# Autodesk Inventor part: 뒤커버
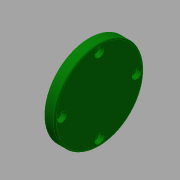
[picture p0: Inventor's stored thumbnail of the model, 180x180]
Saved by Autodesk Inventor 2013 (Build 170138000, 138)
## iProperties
Created: 2015-09
Part Number: 뒤커버
Material: 알루미늄 6061
Document SubType Name: Modeling
Designer: mduedu
Density: 2.71 g/cm^3
Mass: 54.0417 g
Surface Area: 84.9688 cm^2
Volume: 19.9416 cm^3
Author: mduedu
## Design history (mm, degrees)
sketch "스케치1"
  geometry: L1 (-15.5, 47)-(-15.5, 78); L2 (-15.5, 78)-(-22.5, 78); L3 (-22.5, 78)-(-22.5, 63); L4 (-28.5, 63)-(-28.5, 47); L5 (-79.5, 39.5)-(-79.5, 54.5) reference; L6 (48.5, 54.5)-(48.5, 39.5) reference; L7 (-79.5, 47)-(48.5, 47); L8 (-22.5, 63)-(-28.5, 63); L9 (-28.5, 47)-(-15.5, 47); 1 further point
  constraints: 14 end point, 4 midpoint, 3 parallel, 1 collinear, 1 point on line, 1 vertical
  dimensions: "d6" = 62 diameter of L2 L7; "d7" = 7 distance of L1.end L2.end; "d8" = 32 diameter of L3.end L7; "d32" = 13 distance between parallel lines of L1 L4
revolve "회전1" sketch "스케치1" stored, may be unused: angle "d4" = 90 deg
sketch "스케치4"
  geometry: C1 r 31 at (0, 0) reference; 2 further points
  constraints: 1 coincident
hole "구멍3" sketch "스케치4" at (0, 0) diameter "d33" = 22; stored, may be unused: countersink angle "d37" = 90 deg, drill point angle "d39" = 0 deg; dims "d34" = 6, "d35" = 4, "d36" = 2, "d38" = 8
fillet "모깎기4" dims "d40" = 1
chamfer "모따기2" distance "d41" = 1; stored, may be unused: second distance "d42" = 2, angle "d43" = 45 deg
sketch "스케치6" dims "d56" = 52
  geometry: C1 r 31 at (0, 0) reference; 5 further points
  constraints: 2 vertical alignment, 1 coincident, 7 other
  dimensions: "d59" = 360 deg dimension on C1.centre point (0, 26) (derived)
hole "구멍4" sketch "스케치6" at (0, 26), (-26, 0), (0, -26), (26, 0) diameter "d49" = 3.4; stored, may be unused: countersink angle "d53" = 90 deg, drill point angle "d55" = 0 deg; dims "d50" = 6, "d51" = 6.5, "d52" = 3.4, "d54" = 8
fillet "모깎기5" dims "d61" = 3
node "솔리드1"
node "참조1"
node "참조2"
